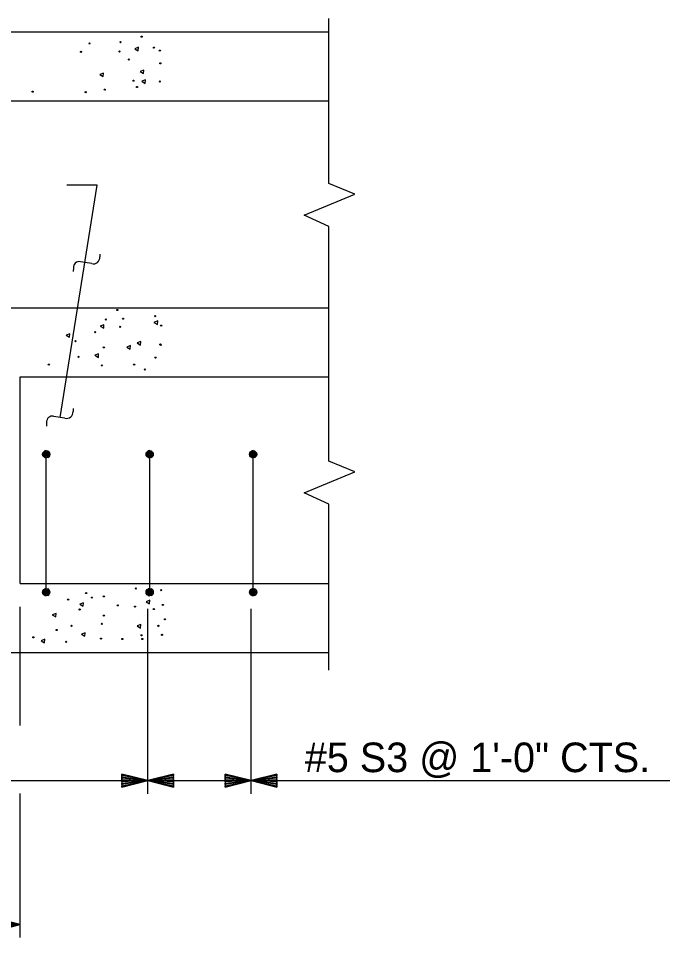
# Model space of a CAD drawing. Extents: x -408 to -23, y -15 to 117.
# Drawn here: x -108.516 to -105.401, y 58.866 to 63.309 of the extents above; entities that cross this region are included whole.
import ezdxf

# ---------------------------------------------------------------- set-up
doc = ezdxf.new("R2010")
doc.units = 0
for name, color, linetype in [('Dimension Lines', 7, 'Continuous'), ('Rebar Lines', 7, 'Continuous'), ('Sup Concrete Girder Lines', 7, 'Continuous'), ('Text', 7, 'Continuous')]:
    doc.layers.add(name, color=color, linetype=linetype)

msp = doc.modelspace()

# ---------------------------------------------------------------- linework, layer by layer
at = {"layer": 'Dimension Lines'}
for p, q in [((-108.1224, 62.1696), (-108.1222, 62.1558)), ((-108.1619, 62.1236), (-108.2165, 62.1323)), ((-108.2506, 62.1032), (-108.2512, 62.0849)), ((-108.2518, 61.4226), (-108.2516, 61.4088)), ((-108.38, 61.3562), (-108.3806, 61.3379)), ((-108.2913, 61.3766), (-108.3458, 61.3853)), ((-108.5081, 59.8919), (-108.5081, 60.4646)), ((-107.8909, 59.5616), (-107.8909, 60.4552)), ((-107.3909, 59.5616), (-107.3909, 60.4552)), ((-111.3909, 59.6246), (-107.8909, 59.6246)), ((-107.8909, 59.6246), (-107.3909, 59.6246)), ((-107.3909, 59.6246), (-104.6899, 59.6246)), ((-108.5081, 58.866), (-108.5081, 59.5621)), ((-111.5081, 58.929), (-108.5081, 58.929))]:
    msp.add_line(p, q, dxfattribs=at)
for points in [[(-108.3137, 61.3802), (-108.1346, 62.5035), (-108.2817, 62.5035)], [(-108.0159, 59.6246), (-108.0159, 59.6309), (-107.8909, 59.6246), (-108.0159, 59.6371), (-108.0159, 59.6434), (-107.8909, 59.6246), (-108.0159, 59.6496), (-108.0159, 59.6559), (-107.8909, 59.6246), (-108.0159, 59.5934), (-108.0159, 59.5996), (-107.8909, 59.6246), (-108.0159, 59.6059), (-108.0159, 59.6121), (-107.8909, 59.6246), (-108.0159, 59.6184), (-108.0159, 59.6559), (-108.0159, 59.5934), (-107.8909, 59.6246), (-108.0159, 59.6559)], [(-107.7659, 59.6246), (-107.7659, 59.6184), (-107.8909, 59.6246), (-107.7659, 59.6121), (-107.7659, 59.6059), (-107.8909, 59.6246), (-107.7659, 59.5996), (-107.7659, 59.5934), (-107.8909, 59.6246), (-107.7659, 59.6559), (-107.7659, 59.6496), (-107.8909, 59.6246), (-107.7659, 59.6434), (-107.7659, 59.6371), (-107.8909, 59.6246), (-107.7659, 59.6309), (-107.7659, 59.5934), (-107.7659, 59.6559), (-107.8909, 59.6246), (-107.7659, 59.5934)], [(-107.5159, 59.6246), (-107.5159, 59.6309), (-107.3909, 59.6246), (-107.5159, 59.6371), (-107.5159, 59.6434), (-107.3909, 59.6246), (-107.5159, 59.6496), (-107.5159, 59.6559), (-107.3909, 59.6246), (-107.5159, 59.5934), (-107.5159, 59.5996), (-107.3909, 59.6246), (-107.5159, 59.6059), (-107.5159, 59.6121), (-107.3909, 59.6246), (-107.5159, 59.6184), (-107.5159, 59.6559), (-107.5159, 59.5934), (-107.3909, 59.6246), (-107.5159, 59.6559)], [(-107.2659, 59.6246), (-107.2659, 59.6184), (-107.3909, 59.6246), (-107.2659, 59.6121), (-107.2659, 59.6059), (-107.3909, 59.6246), (-107.2659, 59.5996), (-107.2659, 59.5934), (-107.3909, 59.6246), (-107.2659, 59.6559), (-107.2659, 59.6496), (-107.3909, 59.6246), (-107.2659, 59.6434), (-107.2659, 59.6371), (-107.3909, 59.6246), (-107.2659, 59.6309), (-107.2659, 59.5934), (-107.2659, 59.6559), (-107.3909, 59.6246), (-107.2659, 59.5934)], [(-108.6331, 58.929), (-108.6331, 58.9352), (-108.5081, 58.929), (-108.6331, 58.9415), (-108.6331, 58.9477), (-108.5081, 58.929), (-108.6331, 58.954), (-108.6331, 58.9602), (-108.5081, 58.929), (-108.6331, 58.8977), (-108.6331, 58.904), (-108.5081, 58.929), (-108.6331, 58.9102), (-108.6331, 58.9165), (-108.5081, 58.929), (-108.6331, 58.9227), (-108.6331, 58.9602), (-108.6331, 58.8977), (-108.5081, 58.929), (-108.6331, 58.9602)]]:
    msp.add_lwpolyline(points, dxfattribs=at)
for centre, radius, start, end in [((-108.1535, 62.1535), 0.0311, 254.3783, 4.1772), ((-108.223, 62.1057), 0.0276, 76.8232, 185.1088), ((-108.2829, 61.4065), 0.0311, 254.3783, 4.1772), ((-108.3523, 61.3587), 0.0276, 76.8232, 185.1088)]:
    msp.add_arc(centre, radius, start, end, dxfattribs=at)
at = {"layer": 'Rebar Lines'}
for p, q in [((-108.3814, 60.5286), (-108.3814, 61.2021)), ((-107.8814, 60.5286), (-107.8814, 61.2021)), ((-107.3814, 60.5286), (-107.3814, 61.2021))]:
    msp.add_line(p, q, dxfattribs=at)
for points in [[(-108.399, 61.2021), (-108.3977, 61.2088), (-108.3939, 61.2145), (-108.3882, 61.2184), (-108.3814, 61.2197), (-108.3747, 61.2184), (-108.369, 61.2145), (-108.3652, 61.2088), (-108.3638, 61.2021), (-108.3652, 61.1953), (-108.369, 61.1896), (-108.3747, 61.1858), (-108.3814, 61.1844), (-108.3882, 61.1858), (-108.3939, 61.1896), (-108.3977, 61.1953), (-108.399, 61.2021), (-108.3814, 61.2021), (-108.3638, 61.2021), (-108.3652, 61.2088), (-108.3814, 61.2021), (-108.369, 61.2145), (-108.3747, 61.2184), (-108.3814, 61.2021), (-108.3814, 61.2197), (-108.3882, 61.2184), (-108.3814, 61.2021), (-108.3939, 61.2145), (-108.3977, 61.2088), (-108.3814, 61.2021), (-108.3977, 61.1953), (-108.3939, 61.1896), (-108.3814, 61.2021), (-108.3882, 61.1858), (-108.3814, 61.1844), (-108.3814, 61.2021), (-108.3747, 61.1858), (-108.369, 61.1896), (-108.3814, 61.2021), (-108.3652, 61.1953)], [(-107.899, 61.2021), (-107.8977, 61.2088), (-107.8939, 61.2145), (-107.8882, 61.2184), (-107.8814, 61.2197), (-107.8747, 61.2184), (-107.869, 61.2145), (-107.8652, 61.2088), (-107.8638, 61.2021), (-107.8652, 61.1953), (-107.869, 61.1896), (-107.8747, 61.1858), (-107.8814, 61.1844), (-107.8882, 61.1858), (-107.8939, 61.1896), (-107.8977, 61.1953), (-107.899, 61.2021), (-107.8814, 61.2021), (-107.8638, 61.2021), (-107.8652, 61.2088), (-107.8814, 61.2021), (-107.869, 61.2145), (-107.8747, 61.2184), (-107.8814, 61.2021), (-107.8814, 61.2197), (-107.8882, 61.2184), (-107.8814, 61.2021), (-107.8939, 61.2145), (-107.8977, 61.2088), (-107.8814, 61.2021), (-107.8977, 61.1953), (-107.8939, 61.1896), (-107.8814, 61.2021), (-107.8882, 61.1858), (-107.8814, 61.1844), (-107.8814, 61.2021), (-107.8747, 61.1858), (-107.869, 61.1896), (-107.8814, 61.2021), (-107.8652, 61.1953)], [(-107.399, 61.2021), (-107.3977, 61.2088), (-107.3939, 61.2145), (-107.3882, 61.2184), (-107.3814, 61.2197), (-107.3747, 61.2184), (-107.369, 61.2145), (-107.3652, 61.2088), (-107.3638, 61.2021), (-107.3652, 61.1953), (-107.369, 61.1896), (-107.3747, 61.1858), (-107.3814, 61.1844), (-107.3882, 61.1858), (-107.3939, 61.1896), (-107.3977, 61.1953), (-107.399, 61.2021), (-107.3814, 61.2021), (-107.3638, 61.2021), (-107.3652, 61.2088), (-107.3814, 61.2021), (-107.369, 61.2145), (-107.3747, 61.2184), (-107.3814, 61.2021), (-107.3814, 61.2197), (-107.3882, 61.2184), (-107.3814, 61.2021), (-107.3939, 61.2145), (-107.3977, 61.2088), (-107.3814, 61.2021), (-107.3977, 61.1953), (-107.3939, 61.1896), (-107.3814, 61.2021), (-107.3882, 61.1858), (-107.3814, 61.1844), (-107.3814, 61.2021), (-107.3747, 61.1858), (-107.369, 61.1896), (-107.3814, 61.2021), (-107.3652, 61.1953)], [(-108.399, 60.5354), (-108.3977, 60.5421), (-108.3939, 60.5478), (-108.3882, 60.5517), (-108.3814, 60.553), (-108.3747, 60.5517), (-108.369, 60.5478), (-108.3652, 60.5422), (-108.3638, 60.5354), (-108.3652, 60.5287), (-108.369, 60.523), (-108.3747, 60.5191), (-108.3814, 60.5177), (-108.3882, 60.5191), (-108.3939, 60.5229), (-108.3977, 60.5286), (-108.399, 60.5354), (-108.3814, 60.5354), (-108.3638, 60.5354), (-108.3652, 60.5422), (-108.3814, 60.5354), (-108.369, 60.5478), (-108.3747, 60.5517), (-108.3814, 60.5354), (-108.3814, 60.553), (-108.3882, 60.5517), (-108.3814, 60.5354), (-108.3939, 60.5478), (-108.3977, 60.5421), (-108.3814, 60.5354), (-108.3977, 60.5286), (-108.3939, 60.5229), (-108.3814, 60.5354), (-108.3882, 60.5191), (-108.3814, 60.5177), (-108.3814, 60.5354), (-108.3747, 60.5191), (-108.369, 60.523), (-108.3814, 60.5354), (-108.3652, 60.5287)], [(-107.899, 60.5354), (-107.8977, 60.5421), (-107.8939, 60.5478), (-107.8882, 60.5517), (-107.8814, 60.553), (-107.8747, 60.5517), (-107.869, 60.5478), (-107.8652, 60.5422), (-107.8638, 60.5354), (-107.8652, 60.5287), (-107.869, 60.523), (-107.8747, 60.5191), (-107.8814, 60.5177), (-107.8882, 60.5191), (-107.8939, 60.5229), (-107.8977, 60.5286), (-107.899, 60.5354), (-107.8814, 60.5354), (-107.8638, 60.5354), (-107.8652, 60.5422), (-107.8814, 60.5354), (-107.869, 60.5478), (-107.8747, 60.5517), (-107.8814, 60.5354), (-107.8814, 60.553), (-107.8882, 60.5517), (-107.8814, 60.5354), (-107.8939, 60.5478), (-107.8977, 60.5421), (-107.8814, 60.5354), (-107.8977, 60.5286), (-107.8939, 60.5229), (-107.8814, 60.5354), (-107.8882, 60.5191), (-107.8814, 60.5177), (-107.8814, 60.5354), (-107.8747, 60.5191), (-107.869, 60.523), (-107.8814, 60.5354), (-107.8652, 60.5287)], [(-107.399, 60.5354), (-107.3977, 60.5421), (-107.3939, 60.5478), (-107.3882, 60.5517), (-107.3814, 60.553), (-107.3747, 60.5517), (-107.369, 60.5478), (-107.3652, 60.5422), (-107.3638, 60.5354), (-107.3652, 60.5287), (-107.369, 60.523), (-107.3747, 60.5191), (-107.3814, 60.5177), (-107.3882, 60.5191), (-107.3939, 60.5229), (-107.3977, 60.5286), (-107.399, 60.5354), (-107.3814, 60.5354), (-107.3638, 60.5354), (-107.3652, 60.5422), (-107.3814, 60.5354), (-107.369, 60.5478), (-107.3747, 60.5517), (-107.3814, 60.5354), (-107.3814, 60.553), (-107.3882, 60.5517), (-107.3814, 60.5354), (-107.3939, 60.5478), (-107.3977, 60.5421), (-107.3814, 60.5354), (-107.3977, 60.5286), (-107.3939, 60.5229), (-107.3814, 60.5354), (-107.3882, 60.5191), (-107.3814, 60.5177), (-107.3814, 60.5354), (-107.3747, 60.5191), (-107.369, 60.523), (-107.3814, 60.5354), (-107.3652, 60.5287)]]:
    msp.add_lwpolyline(points, dxfattribs=at)
at = {"layer": 'Sup Concrete Girder Lines'}
for p, q in [((-112.5375, 63.2438), (-107.0147, 63.2438)), ((-108.8081, 62.9103), (-107.0147, 62.9103)), ((-108.8081, 61.9103), (-107.0147, 61.9103)), ((-108.5081, 61.5771), (-107.0147, 61.5771)), ((-108.5081, 60.5771), (-108.5081, 61.5771)), ((-108.5081, 60.5771), (-107.0147, 60.5771)), ((-111.5081, 60.2438), (-107.0147, 60.2438))]:
    msp.add_line(p, q, dxfattribs=at)
for points in [[(-107.0147, 61.2569), (-107.0147, 62.3028), (-107.134, 62.3575), (-106.8897, 62.4596), (-107.0147, 62.5112), (-107.0147, 63.3088)], [(-107.9363, 63.1523), (-107.9348, 63.1696), (-107.9528, 63.1624), (-107.9363, 63.1523)], [(-108.1063, 63.0273), (-108.1049, 63.0446), (-108.1228, 63.0374), (-108.1063, 63.0273)], [(-107.9117, 63.0417), (-107.9102, 63.0589), (-107.9282, 63.0518), (-107.9117, 63.0417)], [(-107.9035, 62.9946), (-107.902, 63.0118), (-107.92, 63.0047), (-107.9035, 62.9946)], [(-107.8442, 61.829), (-107.8427, 61.8463), (-107.8607, 61.8391), (-107.8442, 61.829)], [(-108.1039, 61.8112), (-108.1024, 61.8285), (-108.1204, 61.8213), (-108.1039, 61.8112)], [(-108.2684, 61.7676), (-108.267, 61.7849), (-108.2849, 61.7777), (-108.2684, 61.7676)], [(-107.975, 61.7101), (-107.9736, 61.7274), (-107.9915, 61.7202), (-107.975, 61.7101)], [(-107.9255, 61.7299), (-107.924, 61.7472), (-107.942, 61.74), (-107.9255, 61.7299)], [(-108.1297, 61.6705), (-108.1282, 61.6877), (-108.1462, 61.6806), (-108.1297, 61.6705)], [(-107.0147, 60.1579), (-107.0147, 60.9611), (-107.134, 61.0158), (-106.8897, 61.1178), (-107.0147, 61.1694), (-107.0147, 61.2569)], [(-108.203, 60.4672), (-108.2015, 60.4845), (-108.2195, 60.4773), (-108.203, 60.4672)], [(-107.8819, 60.4791), (-107.8804, 60.4963), (-107.8984, 60.4892), (-107.8819, 60.4791)], [(-108.3358, 60.4157), (-108.3344, 60.4329), (-108.3523, 60.4258), (-108.3358, 60.4157)], [(-107.9255, 60.3622), (-107.924, 60.3794), (-107.942, 60.3723), (-107.9255, 60.3622)], [(-108.1951, 60.3225), (-108.1936, 60.3398), (-108.2116, 60.3326), (-108.1951, 60.3225)], [(-108.3894, 60.2908), (-108.3879, 60.3081), (-108.4059, 60.3009), (-108.3894, 60.2908)]]:
    msp.add_lwpolyline(points, dxfattribs=at)
for centre in [(-107.9204, 63.2207), (-108.1724, 63.1879), (-108.0228, 63.1941), (-108.2134, 63.147), (-108.027, 63.149), (-107.861, 63.1675), (-107.8323, 63.1531), (-107.9819, 63.1101), (-107.8302, 63.0916), (-107.9594, 63.0076), (-107.8323, 63.0036), (-108.447, 62.9544), (-108.0987, 62.9646), (-107.9429, 62.9769), (-108.1909, 62.9523), (-108.0377, 61.8991), (-108.0932, 61.8535), (-108.01, 61.8575), (-107.8553, 61.8693), (-108.0238, 61.8178), (-107.8256, 61.8238), (-108.1448, 61.7921), (-108.2399, 61.7485), (-108.1032, 61.7187), (-107.8296, 61.7326), (-107.8276, 61.7306), (-108.226, 61.6731), (-107.8534, 61.6691), (-108.3688, 61.6354), (-108.1131, 61.6315), (-107.9564, 61.6354), (-107.9049, 61.6116), (-108.1884, 60.5313), (-108.1607, 60.5095), (-108.1032, 60.5154), (-107.9485, 60.5531), (-107.8256, 60.5452), (-108.2756, 60.4996), (-108.0358, 60.4718), (-107.9525, 60.4659), (-107.8177, 60.4738), (-108.2201, 60.452), (-108.1032, 60.4223), (-107.8613, 60.454), (-108.1131, 60.3826), (-107.8078, 60.4044), (-108.3311, 60.3529), (-108.2598, 60.3727), (-107.8395, 60.3727), (-108.4441, 60.3172), (-108.2855, 60.2954), (-108.117, 60.3113), (-108.0139, 60.3093), (-107.9208, 60.3271), (-107.9168, 60.3093), (-107.8216, 60.3291)]:
    msp.add_circle(centre, 0.00273, dxfattribs=at)

# ---------------------------------------------------------------- texts
at = {"layer": 'Text'}
msp.add_text('#5 S3 @ 1\'-0" CTS.', height=0.143021, dxfattribs=at).set_placement((-107.1311, 59.6657))

doc.saveas('drawing.dxf')
